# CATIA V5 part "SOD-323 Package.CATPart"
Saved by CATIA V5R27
Part number: SOD-323 Package
Definition: SOD-323 Package
Nomenclature: SOD-323 Package v1
Source: Unknown
Bounding box of the stored display mesh (mm): x -0.723 to 0.723, y 0.02 to 1.17, z -1.35 to 1.35
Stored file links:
  E:\university\my-thesis\My Thesis Publication\Final-Updata\CAD\SOD-323 Package.CATPart
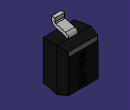
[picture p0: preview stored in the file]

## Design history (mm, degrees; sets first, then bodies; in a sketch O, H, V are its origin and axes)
Body1 "Body1" (main body)
  Solid1: solid without history
Body2 "Body2"
  Solid2: solid without history
Body3 "Body3"
  Solid3: solid without history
